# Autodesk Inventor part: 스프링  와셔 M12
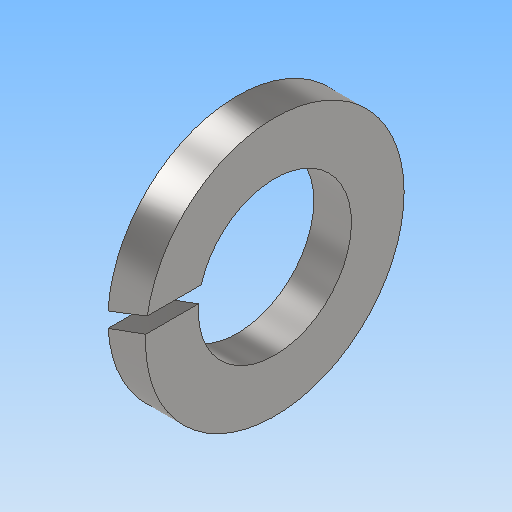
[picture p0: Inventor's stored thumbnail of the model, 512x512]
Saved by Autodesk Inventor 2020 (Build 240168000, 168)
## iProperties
Created: 2024-07
Part Number: 스프링  와셔 M12
Material: 강철, 연강
Description: 스프링 잠금 와셔
Document SubType Name: Modeling
Designer: oem
Density: 7.85 g/cm^3
Appearance: 기본값
Author: jhkim
Sending System: Autodesk Inventor 2025
Preprocessor: ST-DEVELOPER v20
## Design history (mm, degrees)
feature "Solid1"
node "솔리드1"
